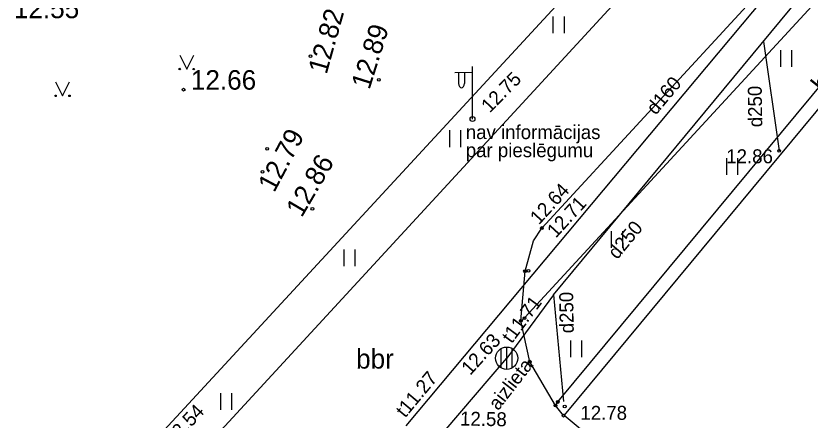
# Model space of a CAD drawing. Extents: x 503877 to 504025, y 304562 to 304725.
# Drawn here: x 503881.56 to 503910.05, y 304583.96 to 304598.46 of the extents above; entities that cross this region are included whole.
import ezdxf

# ---------------------------------------------------------------- set-up
doc = ezdxf.new("R2010")
doc.units = 0
for name, color, linetype in [('APGS_ELEM_####_####_#', 7, 'Continuous'), ('APGS_ELEM_####_TKST_#', 7, 'Continuous'), ('BUVE_EKAS_####_####_#', 7, 'Continuous'), ('CELI_CAPM_####_####_#', 7, 'Continuous'), ('CELI_CMAL_####_####_#', 7, 'Continuous'), ('CELI_CSEG_####_TKST_#', 7, 'Continuous'), ('LKAN_ELEM_####_####_#', 7, 'Continuous'), ('LKAN_ELEM_PAST_TKST_#', 7, 'Continuous'), ('LKAN_VADP_PAST_####_#', 7, 'Continuous'), ('LKAN_VADP_PAST_TKST_#', 7, 'Continuous'), ('NORB_ZOGS_ZSTP_####_#', 7, 'Continuous'), ('RELJ_AATZ_####_TKST_#', 7, 'Continuous'), ('RELJ_ELEM_####_####_#', 7, 'Continuous'), ('SKAN_ELEM_PAST_TKST_#', 7, 'Continuous'), ('SKAN_VADP_PAST_####_#', 7, 'Continuous'), ('SKAN_VADP_PAST_TKST_#', 7, 'Continuous'), ('TERT_ELEM_####_####_#', 7, 'Continuous')]:
    doc.layers.add(name, color=color, linetype=linetype)

msp = doc.modelspace()

# ---------------------------------------------------------------- linework, layer by layer
at = {"layer": 'APGS_ELEM_####_####_#'}
for p, q in [((503897.943, 304594.761), (503897.943, 304596.6435448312)), ((503897.943, 304596.42754483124), (503897.308, 304596.42254483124)), ((503897.443, 304596.4235448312), (503897.443, 304596.03154483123)), ((503897.653, 304596.4255448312), (503897.653, 304596.03154483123))]:
    msp.add_line(p, q, dxfattribs=at)
msp.add_circle((503897.943, 304594.761), 0.09, dxfattribs=at)
msp.add_ellipse((503897.548, 304596.03154483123), major_axis=(9.238021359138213e-18, 0.15086833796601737), ratio=0.6959710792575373, start_param=1.5707963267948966, end_param=4.71238898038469, dxfattribs=at)
at = {"layer": 'BUVE_EKAS_####_####_#'}
for p, q in [((503924.5556478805, 304612.2466334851), (503901.22431950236, 304584.1408637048)), ((503901.22431950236, 304584.1408637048), (503906.0783986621, 304580.1113667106))]:
    msp.add_line(p, q, dxfattribs=at)
at = {"layer": 'CELI_CAPM_####_####_#'}
for p, q in [((503923.37700000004, 304620.99), (503883.259, 304577.462)), ((503900.43, 304590.8510000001), (503913.979, 304605.548)), ((503900.1334014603, 304590.3914911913), (503900.43, 304590.8510000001)), ((503899.825, 304589.306), (503900.1334014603, 304590.3914911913)), ((503899.678, 304587.521), (503899.825, 304589.306)), ((503899.994, 304586.055), (503899.678, 304587.521)), ((503900.917, 304584.488), (503899.994, 304586.055)), ((503901.207, 304584.12), (503900.917, 304584.488))]:
    msp.add_line(p, q, dxfattribs=at)
at = {"layer": 'CELI_CMAL_####_####_#'}
for p, q in [((503921.326, 304610.998), (503899.6804941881, 304587.48182042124)), ((503901.003, 304584.612), (503912.215, 304598.12599999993)), ((503900.917, 304584.488), (503901.003, 304584.612))]:
    msp.add_line(p, q, dxfattribs=at)
at = {"layer": 'LKAN_ELEM_####_####_#'}
for p, q in [((503898.969, 304585.8335898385), (503898.969, 304586.5264101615)), ((503899.169, 304585.78), (503899.169, 304586.58)), ((503899.369, 304585.8335898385), (503899.369, 304586.5264101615))]:
    msp.add_line(p, q, dxfattribs=at)
msp.add_circle((503899.169, 304586.18), 0.4, dxfattribs=at)
at = {"layer": 'LKAN_VADP_PAST_####_#'}
for p, q in [((503900.8515863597, 304588.45744584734), (503920.23436525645, 304611.8542670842)), ((503908.37585379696, 304597.5399381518), (503908.943, 304593.625)), ((503900.8515863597, 304588.45744584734), (503899.169, 304586.18)), ((503900.8515863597, 304588.45744584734), (503901.211, 304584.627)), ((503896.922, 304583.556), (503899.169, 304586.18))]:
    msp.add_line(p, q, dxfattribs=at)
at = {"layer": 'NORB_ZOGS_ZSTP_####_#'}
msp.add_line((503882.20785585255, 304578.5445974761), (503916.428, 304615.582), dxfattribs=at)
at = {"layer": 'RELJ_ELEM_####_####_#'}
for centre in [(503892.129, 304597.018), (503894.585, 304596.165), (503887.579, 304595.814), (503890.576, 304593.688), (503908.943, 304593.625), (503890.405, 304592.868), (503892.197, 304591.542), (503900.43, 304590.8510000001), (503899.825, 304589.306), (503899.952, 304589.313), (503899.678, 304587.521), (503899.804, 304587.616), (503899.994, 304586.055), (503901.003, 304584.612), (503900.917, 304584.488), (503901.249, 304584.449), (503901.207, 304584.12)]:
    msp.add_circle(centre, 0.05, dxfattribs=at)
at = {"layer": 'SKAN_VADP_PAST_####_#'}
msp.add_line((503895.55985508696, 304583.75142224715), (503913.8271784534, 304605.5682143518), dxfattribs=at)
at = {"layer": 'TERT_ELEM_####_####_#'}
for p, q in [((503900.8380685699, 304597.84126877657), (503900.8380685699, 304598.44126877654)), ((503901.2380685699, 304597.84126877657), (503901.2380685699, 304598.44126877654)), ((503909.00120875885, 304596.6366986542), (503909.00120875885, 304597.23669865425)), ((503909.4012087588, 304596.6366986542), (503909.4012087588, 304597.23669865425)), ((503887.44025724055, 304597.0532218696), (503887.69025724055, 304596.5532218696)), ((503887.69025724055, 304596.5532218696), (503887.94025724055, 304597.0532218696)), ((503882.9846756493, 304596.093489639), (503883.2346756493, 304595.593489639)), ((503883.2346756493, 304595.593489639), (503883.4846756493, 304596.093489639)), ((503897.12279322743, 304593.75620488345), (503897.12279322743, 304594.3562048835)), ((503897.52279322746, 304593.75620488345), (503897.52279322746, 304594.3562048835)), ((503907.0650793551, 304592.7611252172), (503907.0650793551, 304593.3611252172)), ((503907.46507935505, 304592.7611252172), (503907.46507935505, 304593.3611252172)), ((503902.93118143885, 304590.14249451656), (503902.93118143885, 304590.74249451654)), ((503903.3311814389, 304590.14249451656), (503903.3311814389, 304590.74249451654)), ((503893.33276385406, 304589.4766141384), (503893.33276385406, 304590.07661413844)), ((503893.73276385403, 304589.4766141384), (503893.73276385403, 304590.07661413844)), ((503901.4660024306, 304586.21454846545), (503901.4660024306, 304586.8145484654)), ((503901.86600243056, 304586.21454846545), (503901.86600243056, 304586.8145484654)), ((503888.91246351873, 304584.32303221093), (503888.91246351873, 304584.92303221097)), ((503889.31246351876, 304584.32303221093), (503889.31246351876, 304584.92303221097))]:
    msp.add_line(p, q, dxfattribs=at)
for centre, radius in [((503887.43997733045, 304596.5527715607), 0.02800000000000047), ((503887.93997733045, 304596.5527715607), 0.02630589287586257), ((503882.98439574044, 304595.5930393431), 0.02800000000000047), ((503883.48439574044, 304595.5930393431), 0.02630589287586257)]:
    msp.add_circle(centre, radius, dxfattribs=at)

# ---------------------------------------------------------------- texts
at = {"layer": 'APGS_ELEM_####_TKST_#'}
for s, p in [('nav informācijas', (503897.70072545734, 304594.04178209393)), ('par pieslēgumu', (503897.70072545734, 304593.39178209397))]:
    msp.add_text(s, height=0.5, dxfattribs=at).set_placement(p)
at = {"layer": 'CELI_CSEG_####_TKST_#'}
msp.add_text('bbr', height=0.7000000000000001, rotation=50.96132219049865, dxfattribs=at).set_placement((503910.5777907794, 304595.6208956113))
msp.add_text('bbr', height=0.7000000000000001, dxfattribs=at).set_placement((503893.7663736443, 304585.80827891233))
at = {"layer": 'LKAN_ELEM_PAST_TKST_#'}
for s, height, rotation, p in [(' 12.63', 0.5, 47.683050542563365, (503897.73657475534, 304585.40723322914)), (' 12.58', 0.49999999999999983, 359.0075522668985, (503897.3069403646, 304583.7693842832))]:
    msp.add_text(s, height=height, rotation=rotation, dxfattribs=at).set_placement(p)
at = {"layer": 'LKAN_VADP_PAST_TKST_#'}
for s, rotation, p in [('d250', 90.9246138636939, (503908.33923698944, 304594.4700672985)), ('d250', 50.360411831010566, (503903.1328503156, 304589.69799426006)), ('t11.71', 53.45775380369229, (503899.3484641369, 304586.68147238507)), ('d250', 90.9246138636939, (503901.5745929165, 304587.0786111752))]:
    msp.add_text(s, height=0.5, rotation=rotation, dxfattribs=at).set_placement(p)
at = {"layer": 'RELJ_AATZ_####_TKST_#'}
for s, height, p in [(' 12.55', 0.700002, (503881.23000000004, 304598.377)), (' 12.66', 0.700002, (503887.579, 304595.814)), (' 12.86', 0.5, (503906.85928334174, 304593.17376947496)), (' 12.78', 0.5, (503901.6261410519, 304583.971151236))]:
    msp.add_text(s, height=height, dxfattribs=at).set_placement(p)
for s, height, rotation, p in [(' 12.82', 0.700002, 74.24882500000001, (503892.636, 304596.089)), (' 12.89', 0.700002, 72.47443055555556, (503894.166, 304595.54)), (' 12.75', 0.5, 45.46780892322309, (503898.4284501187, 304594.8242888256)), (' 12.79', 0.700002, 61.927513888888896, (503890.704, 304591.864)), (' 12.86', 0.7000020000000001, 59.65675, (503891.684, 304590.976)), (' 12.64', 0.5, 47.25753651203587, (503900.1961625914, 304590.80578262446)), (' 12.71', 0.5, 47.417257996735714, (503900.8087660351, 304590.333819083)), (' 12.54', 0.4999999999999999, 46.91856968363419, (503887.0881537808, 304582.88013882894))]:
    msp.add_text(s, height=height, rotation=rotation, dxfattribs=at).set_placement(p)
at = {"layer": 'SKAN_ELEM_PAST_TKST_#'}
msp.add_text('aizlieta', height=0.5, rotation=52.15452445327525, dxfattribs=at).set_placement((503898.8618210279, 304584.2769683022))
at = {"layer": 'SKAN_VADP_PAST_TKST_#'}
for s, p in [('d160', (503904.51374960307, 304594.87834691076)), ('t11.27', (503895.5246161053, 304584.01654001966))]:
    msp.add_text(s, height=0.5, rotation=50.06037140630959, dxfattribs=at).set_placement(p)

doc.saveas('drawing.dxf')
